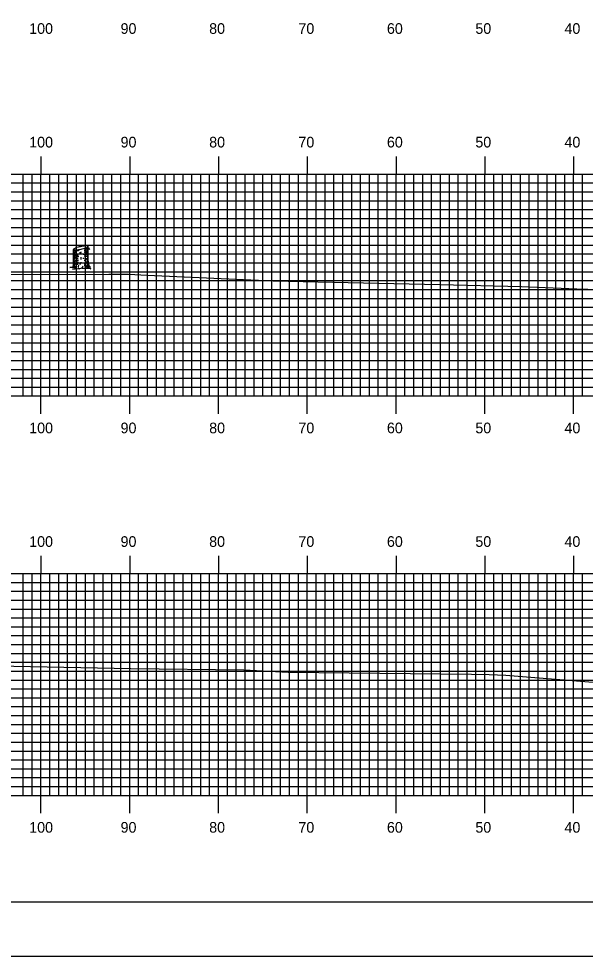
# Model space of a CAD drawing. Extents: x 1772809 to 1773153, y 442591 to 442811.
# Drawn here: x 1772872.6 to 1772936.4, y 442590.5 to 442696.2 of the extents above; entities that cross this region are included whole.
import ezdxf

# ---------------------------------------------------------------- set-up
doc = ezdxf.new("R2010")
doc.units = 0
for name, color, linetype in [('BORDER', 7, 'Continuous'), ('H_V ANNOTATION', 7, 'Continuous'), ('M_Trees_Conifer_Pay', 7, 'Continuous'), ('MAJOR', 7, 'Continuous'), ('MINOR', 7, 'Continuous'), ('PLOT BOUNDARY', 7, 'Continuous'), ('S_Roadway_Centerline', 7, 'Continuous')]:
    doc.layers.add(name, color=color, linetype=linetype)

msp = doc.modelspace()

# ---------------------------------------------------------------- linework, layer by layer
at = {"layer": 'BORDER'}
msp.add_lwpolyline([(1772825.52, 442596.67), (1773145.52, 442596.67), (1773145.52, 442806.67), (1772825.52, 442806.67)], close=True, dxfattribs=at)
at = {"layer": 'M_Trees_Conifer_Pay'}
for p, q in [((1772878.78, 442668.46), (1772878.78, 442670.18)), ((1772878.82, 442670.15), (1772878.82, 442669.67)), ((1772878.88, 442670.13), (1772878.88, 442670.04)), ((1772879.01, 442670.13), (1772879.01, 442669.89)), ((1772879.23, 442670.15), (1772879.23, 442669.98)), ((1772880.02, 442670.19), (1772880.02, 442669.99)), ((1772880.25, 442670.38), (1772880.25, 442670.16)), ((1772880.25, 442670.07), (1772880.25, 442670.03)), ((1772880.37, 442670.45), (1772880.37, 442670.28)), ((1772880.37, 442670.22), (1772880.37, 442670.09)), ((1772880.44, 442668.87), (1772880.44, 442670.52)), ((1772878.82, 442669.61), (1772878.82, 442669.3)), ((1772878.82, 442669.25), (1772878.82, 442668.76)), ((1772878.88, 442669.96), (1772878.88, 442669.76)), ((1772878.88, 442669.7), (1772878.88, 442669.5)), ((1772878.88, 442669.45), (1772878.88, 442669.12)), ((1772878.88, 442669.06), (1772878.88, 442668.93)), ((1772879.01, 442669.85), (1772879.01, 442669.78)), ((1772879.01, 442669.38), (1772879.01, 442669.24)), ((1772879.23, 442669.74), (1772879.23, 442669.5)), ((1772879.23, 442669.26), (1772879.23, 442669.11)), ((1772879.23, 442669.06), (1772879.23, 442668.89)), ((1772879.63, 442669.92), (1772879.63, 442669.82)), ((1772879.63, 442669.3), (1772879.63, 442669.23)), ((1772879.63, 442669.2), (1772879.63, 442669.05)), ((1772880.02, 442669.93), (1772880.02, 442669.84)), ((1772880.02, 442669.5), (1772880.02, 442669.39)), ((1772880.02, 442669.02), (1772880.02, 442668.88)), ((1772880.25, 442669.69), (1772880.25, 442669.56)), ((1772880.25, 442669.45), (1772880.25, 442669.34)), ((1772880.25, 442669.2), (1772880.25, 442669.06)), ((1772880.31, 442669.89), (1772880.26, 442669.83)), ((1772880.37, 442669.9), (1772880.37, 442669.56)), ((1772880.37, 442669.53), (1772880.37, 442669.37)), ((1772880.37, 442669.32), (1772880.37, 442669.1)), ((1772880.37, 442669.07), (1772880.37, 442669)), ((1772878.82, 442668.71), (1772878.82, 442668.46)), ((1772878.88, 442668.83), (1772878.88, 442668.45)), ((1772879.01, 442668.97), (1772879.01, 442668.82)), ((1772879.01, 442668.56), (1772879.01, 442668.47)), ((1772879.01, 442668.07), (1772879.17, 442668.13)), ((1772879.23, 442668.61), (1772879.23, 442668.46)), ((1772879.44, 442668), (1772879.32, 442668.07)), ((1772879.63, 442668.76), (1772879.63, 442668.61)), ((1772880.02, 442668.64), (1772880.02, 442668.56)), ((1772880.25, 442668.83), (1772880.25, 442668.66)), ((1772880.37, 442668.96), (1772880.37, 442668.78))]:
    msp.add_line(p, q, dxfattribs=at)
for points in [[(1772880.26, 442670.02), (1772880.29, 442669.94), (1772880.34, 442670), (1772880.4, 442670.07), (1772880.49, 442670.26), (1772880.56, 442670.31), (1772880.59, 442670.31)], [(1772880.27, 442669.76), (1772880.31, 442669.89), (1772880.37, 442670.01), (1772880.4, 442670.07), (1772880.47, 442670.22)], [(1772880.49, 442670.25), (1772880.56, 442670.26), (1772880.63, 442670.16)], [(1772878.96, 442669.49), (1772878.95, 442669.58), (1772878.99, 442669.56), (1772878.99, 442669.47)], [(1772880.09, 442669.09), (1772880.11, 442669.01), (1772880.15, 442669.02), (1772880.14, 442669.19)], [(1772880.22, 442669.98), (1772880.19, 442669.89), (1772880.19, 442669.83), (1772880.22, 442669.76)], [(1772880.44, 442668.87), (1772880.49, 442668.61), (1772880.51, 442668.34), (1772880.57, 442668.21), (1772880.7, 442668.18), (1772880.47, 442668.14), (1772880.47, 442668.14), (1772880.48, 442668.09), (1772880.72, 442668), (1772880.45, 442668.02), (1772880.09, 442668.04), (1772879.77, 442668.03), (1772879.78, 442668.11), (1772879.63, 442668.03), (1772879.44, 442668), (1772879.47, 442667.94), (1772879.2, 442667.98), (1772878.98, 442667.95), (1772878.69, 442667.97), (1772878.98, 442668.03), (1772879.01, 442668.07), (1772878.84, 442668.13), (1772878.61, 442668.14), (1772878.37, 442668.14), (1772878.71, 442668.19), (1772878.75, 442668.27), (1772878.78, 442668.46)], [(1772878.82, 442668.41), (1772878.8, 442668.34), (1772878.78, 442668.24)], [(1772878.9, 442668.39), (1772878.91, 442668.28), (1772878.86, 442668.19), (1772878.84, 442668.13)], [(1772879.07, 442668.42), (1772879.07, 442668.29), (1772878.98, 442668.19)], [(1772879.29, 442668.18), (1772879.36, 442668.27), (1772879.39, 442668.41)], [(1772879.78, 442668.11), (1772879.85, 442668.25), (1772879.86, 442668.35)], [(1772880.03, 442668.48), (1772880.04, 442668.35), (1772880.12, 442668.31)], [(1772880.31, 442668.09), (1772880.29, 442668.23), (1772880.22, 442668.36)], [(1772880.27, 442668.58), (1772880.34, 442668.48), (1772880.35, 442668.3), (1772880.47, 442668.14)], [(1772880.37, 442668.73), (1772880.37, 442668.58), (1772880.42, 442668.51), (1772880.43, 442668.32)]]:
    msp.add_lwpolyline(points, dxfattribs=at)
for centre, radius, start, end in [((1772878.85, 442670.16), 0.0817, 132.3887, 146.7194), ((1772878.83, 442670.17), 0.0527, 146.7194, 156.5158), ((1772878.81, 442670.18), 0.0314, 156.5158, 169.2194), ((1772878.8, 442670.18), 0.0264, 169.2194, 180.0315), ((1772878.8, 442670.18), 0.0226, 180.0315, 191.7194), ((1772878.8, 442670.18), 0.0226, 191.7194, 203.4074), ((1772878.8, 442670.18), 0.0264, 203.4074, 214.2194), ((1772878.81, 442670.19), 0.0314, 214.2194, 226.923), ((1772878.82, 442670.2), 0.0527, 226.923, 236.7194), ((1772878.84, 442670.23), 0.0817, 236.7194, 251.0501), ((1772878.97, 442670.03), 0.251, 124.2194, 132.3887), ((1772878.89, 442670.39), 0.251, 251.0501, 259.2194), ((1772879.28, 442669.58), 0.802, 108.0594, 124.2194), ((1772879, 442670.93), 0.802, 259.2194, 275.3794), ((1772880.63, 442665.42), 5.18, 101.7194, 108.0594), ((1772878.58, 442675.29), 5.18, 275.3794, 281.7194), ((1772879.61, 442674.19), 4.12, 264.6955, 266.7331), ((1772880.63, 442665.42), 5.18, 95.3794, 101.7194), ((1772878.58, 442675.29), 5.18, 281.7194, 288.0594), ((1772879.61, 442674.19), 4.12, 276.238, 278.1032), ((1772880.22, 442669.77), 0.802, 79.2194, 95.3794), ((1772879.94, 442671.12), 0.802, 288.0594, 304.2194), ((1772880.11, 442670.68), 0.571, 278.1032, 284.3667), ((1772880.11, 442670.83), 0.571, 284.4317, 292.4132), ((1772880.33, 442670.31), 0.251, 71.0501, 79.2194), ((1772880.11, 442670.68), 0.571, 297.0237, 300), ((1772880.25, 442670.67), 0.251, 304.2194, 312.3887), ((1772880.31, 442670.49), 0.172, 300, 311.2506), ((1772880.31, 442670.33), 0.172, 300, 311.2506), ((1772880.38, 442670.47), 0.0817, 56.7194, 71.0501), ((1772880.4, 442670.5), 0.0527, 46.923, 56.7194), ((1772880.37, 442670.54), 0.0817, 312.3887, 326.7194), ((1772880.38, 442670.4), 0.0624, 311.2506, 330), ((1772880.38, 442670.25), 0.0624, 311.2506, 330), ((1772880.41, 442670.51), 0.0314, 34.2194, 46.923), ((1772880.39, 442670.53), 0.0527, 326.7194, 336.5158), ((1772880.42, 442670.52), 0.0226, 11.7194, 23.4074), ((1772880.41, 442670.52), 0.0264, 23.4074, 34.2194), ((1772880.41, 442670.52), 0.0264, 349.2194, 0.0315), ((1772880.42, 442670.52), 0.0226, 0.0315, 11.7194), ((1772880.41, 442670.52), 0.0314, 336.5158, 349.2194), ((1772880.41, 442670.39), 0.0334, 343.9485, 354.2151), ((1772880.4, 442670.39), 0.0441, 330, 343.9485), ((1772880.4, 442670.24), 0.0441, 330, 343.9485), ((1772880.41, 442670.24), 0.0334, 343.9485, 354.2151), ((1772878.81, 442670), 0.0334, 163.9485, 180), ((1772878.81, 442670), 0.0334, 180, 196.0515), ((1772878.82, 442670.01), 0.0441, 196.0515, 210), ((1772878.83, 442670.02), 0.0624, 210, 228.7494), ((1772878.81, 442669.56), 0.0334, 163.9485, 180), ((1772878.81, 442669.56), 0.0334, 180, 196.0515), ((1772878.82, 442669.56), 0.0441, 196.0515, 210), ((1772878.83, 442669.57), 0.0624, 210, 228.7494), ((1772878.81, 442669.35), 0.0334, 163.9485, 180), ((1772878.81, 442669.35), 0.0334, 180, 196.0515), ((1772878.82, 442669.35), 0.0441, 196.0515, 210), ((1772878.83, 442669.36), 0.0624, 210, 228.7494), ((1772878.81, 442669.11), 0.0334, 163.9485, 180), ((1772878.81, 442669.11), 0.0334, 180, 196.0515), ((1772878.82, 442669.11), 0.0441, 196.0515, 210), ((1772878.83, 442669.12), 0.0624, 210, 228.7494), ((1772878.91, 442670.1), 0.172, 228.7494, 240), ((1772878.91, 442669.65), 0.172, 228.7494, 240), ((1772878.91, 442669.44), 0.172, 228.7494, 240), ((1772878.91, 442669.21), 0.172, 228.7494, 240), ((1772879.11, 442670.44), 0.571, 240, 240.3367), ((1772879.11, 442670.23), 0.571, 240, 247.0587), ((1772879.11, 442670), 0.571, 240, 240.3367), ((1772879.11, 442669.79), 0.571, 240, 246.8597), ((1772879.11, 442669.55), 0.571, 240, 246.8597), ((1772879.11, 442670.44), 0.571, 246.8597, 257.9846), ((1772879.11, 442669.79), 0.571, 259.2707, 261.8968), ((1772879.61, 442673.31), 4.12, 261.8968, 263.1474), ((1772879.61, 442673.52), 4.12, 264.081, 266.6676), ((1772879.61, 442673.96), 4.12, 268.0751, 270), ((1772879.61, 442673.96), 4.12, 270, 270.3581), ((1772879.61, 442673.31), 4.12, 270, 270.3581), ((1772879.61, 442673.31), 4.12, 273.1493, 275.4569), ((1772879.61, 442673.75), 4.12, 273.7052, 275.9504), ((1772879.61, 442673.96), 4.12, 275.7849, 277.0558), ((1772879.61, 442673.52), 4.12, 277.6125, 278.1032), ((1772880.11, 442670), 0.571, 278.1032, 286.9296), ((1772880.11, 442670.23), 0.571, 284.4493, 297.0429), ((1772880.11, 442669.55), 0.571, 285.3983, 297.1896), ((1772880.11, 442670), 0.571, 297.1896, 300), ((1772880.11, 442669.79), 0.571, 297.1896, 300), ((1772880.31, 442669.65), 0.172, 300, 311.2506), ((1772880.31, 442669.44), 0.172, 300, 311.2506), ((1772880.38, 442669.57), 0.0624, 311.2506, 330), ((1772880.38, 442669.36), 0.0624, 311.2506, 330), ((1772880.4, 442669.56), 0.0441, 330, 343.9485), ((1772880.4, 442669.35), 0.0441, 330, 343.9485), ((1772880.41, 442669.79), 0.0334, 343.9485, 354.2151), ((1772880.41, 442669.56), 0.0334, 343.9485, 354.2151), ((1772880.41, 442669.35), 0.0334, 343.9485, 354.2151), ((1772878.81, 442668.91), 0.0334, 163.9485, 180), ((1772878.81, 442668.72), 0.0334, 163.9485, 180), ((1772878.81, 442668.72), 0.0334, 180, 196.0515), ((1772878.82, 442668.72), 0.0441, 196.0515, 210), ((1772878.83, 442668.73), 0.0624, 210, 228.7494), ((1772878.81, 442668.5), 0.0334, 163.9485, 180), ((1772878.81, 442668.5), 0.0334, 180, 196.0515), ((1772878.82, 442668.5), 0.0441, 196.0515, 210), ((1772878.83, 442668.51), 0.0624, 210, 228.7494), ((1772878.91, 442668.81), 0.172, 228.7494, 240), ((1772878.91, 442668.59), 0.172, 228.7494, 240), ((1772879.1, 442669.36), 0.571, 241.2369, 248.0268), ((1772879.11, 442669.16), 0.571, 240, 246.8597), ((1772879.11, 442668.94), 0.571, 240, 244.5314), ((1772879.61, 442672.45), 4.12, 262.4438, 263.512), ((1772879.61, 442672.87), 4.12, 263.4991, 265.8397), ((1772879.61, 442673.07), 4.12, 264.716, 266.3193), ((1772879.61, 442672.67), 4.12, 267.8117, 270), ((1772879.61, 442672.67), 4.12, 270, 270.1328), ((1772879.61, 442672.67), 4.12, 275.7849, 276.7896), ((1772879.61, 442672.45), 4.12, 277.3684, 278.1032), ((1772880.11, 442668.94), 0.571, 278.1032, 281.637), ((1772880.11, 442669.16), 0.571, 288.5067, 297.2721), ((1772880.11, 442669.35), 0.571, 289.2907, 300), ((1772880.31, 442669.01), 0.172, 300, 311.2506), ((1772880.31, 442668.59), 0.172, 300, 311.2506), ((1772880.38, 442668.93), 0.0624, 311.2506, 330), ((1772880.38, 442668.51), 0.0624, 311.2506, 330), ((1772880.4, 442668.92), 0.0441, 330, 343.9485), ((1772880.4, 442668.5), 0.0441, 330, 343.9485), ((1772880.41, 442668.91), 0.0334, 343.9485, 354.2151), ((1772880.41, 442668.5), 0.0334, 343.9485, 354.2151)]:
    msp.add_arc(centre, radius, start, end, dxfattribs=at)
at = {"layer": 'MAJOR'}
for p, q in [((1772875.12, 442680.67), (1772875.12, 442678.67)), ((1772885.12, 442680.67), (1772885.12, 442678.67)), ((1772895.12, 442680.67), (1772895.12, 442678.67)), ((1772905.12, 442680.67), (1772905.12, 442678.67)), ((1772915.12, 442680.67), (1772915.12, 442678.67)), ((1772925.12, 442680.67), (1772925.12, 442678.67)), ((1772935.12, 442680.67), (1772935.12, 442678.67)), ((1772835.12, 442678.67), (1773115.12, 442678.67)), ((1772835.12, 442678.67), (1773115.12, 442678.67)), ((1772875.12, 442653.67), (1772875.12, 442678.67)), ((1772885.12, 442653.67), (1772885.12, 442678.67)), ((1772895.12, 442653.67), (1772895.12, 442678.67)), ((1772905.12, 442653.67), (1772905.12, 442678.67)), ((1772915.12, 442653.67), (1772915.12, 442678.67)), ((1772925.12, 442653.67), (1772925.12, 442678.67)), ((1772935.12, 442653.67), (1772935.12, 442678.67)), ((1772835.12, 442673.67), (1773115.12, 442673.67)), ((1772835.12, 442668.67), (1773115.12, 442668.67)), ((1772835.12, 442663.67), (1773115.12, 442663.67)), ((1772835.12, 442658.67), (1773115.12, 442658.67)), ((1772835.12, 442653.67), (1773115.12, 442653.67)), ((1772835.12, 442653.67), (1773115.12, 442653.67)), ((1772875.12, 442651.66), (1772875.12, 442653.67)), ((1772885.12, 442651.66), (1772885.12, 442653.67)), ((1772895.12, 442651.66), (1772895.12, 442653.67)), ((1772905.12, 442651.66), (1772905.12, 442653.67)), ((1772915.12, 442651.66), (1772915.12, 442653.67)), ((1772925.12, 442651.66), (1772925.12, 442653.67)), ((1772935.12, 442651.66), (1772935.12, 442653.67)), ((1772875.12, 442635.67), (1772875.12, 442633.67)), ((1772885.12, 442635.67), (1772885.12, 442633.67)), ((1772895.12, 442635.67), (1772895.12, 442633.67)), ((1772905.12, 442635.67), (1772905.12, 442633.67)), ((1772915.12, 442635.67), (1772915.12, 442633.67)), ((1772925.12, 442635.67), (1772925.12, 442633.67)), ((1772935.12, 442635.67), (1772935.12, 442633.67)), ((1772835.12, 442633.67), (1773115.12, 442633.67)), ((1772835.12, 442633.67), (1773115.12, 442633.67)), ((1772875.12, 442608.67), (1772875.12, 442633.67)), ((1772885.12, 442608.67), (1772885.12, 442633.67)), ((1772895.12, 442608.67), (1772895.12, 442633.67)), ((1772905.12, 442608.67), (1772905.12, 442633.67)), ((1772915.12, 442608.67), (1772915.12, 442633.67)), ((1772925.12, 442608.67), (1772925.12, 442633.67)), ((1772935.12, 442608.67), (1772935.12, 442633.67)), ((1772835.12, 442628.67), (1773115.12, 442628.67)), ((1772835.12, 442623.67), (1773115.12, 442623.67)), ((1772835.12, 442618.67), (1773115.12, 442618.67)), ((1772835.12, 442613.67), (1773115.12, 442613.67)), ((1772835.12, 442608.67), (1773115.12, 442608.67)), ((1772835.12, 442608.67), (1773115.12, 442608.67)), ((1772875.12, 442606.66), (1772875.12, 442608.67)), ((1772885.12, 442606.66), (1772885.12, 442608.67)), ((1772895.12, 442606.66), (1772895.12, 442608.67)), ((1772905.12, 442606.66), (1772905.12, 442608.67)), ((1772915.12, 442606.66), (1772915.12, 442608.67)), ((1772925.12, 442606.66), (1772925.12, 442608.67)), ((1772935.12, 442606.66), (1772935.12, 442608.67))]:
    msp.add_line(p, q, dxfattribs=at)
at = {"layer": 'MINOR'}
for p, q in [((1772873.12, 442653.67), (1772873.12, 442678.67)), ((1772874.12, 442653.67), (1772874.12, 442678.67)), ((1772876.12, 442653.67), (1772876.12, 442678.67)), ((1772877.12, 442653.67), (1772877.12, 442678.67)), ((1772878.12, 442653.67), (1772878.12, 442678.67)), ((1772879.12, 442653.67), (1772879.12, 442678.67)), ((1772880.12, 442653.67), (1772880.12, 442678.67)), ((1772881.12, 442653.67), (1772881.12, 442678.67)), ((1772882.12, 442653.67), (1772882.12, 442678.67)), ((1772883.12, 442653.67), (1772883.12, 442678.67)), ((1772884.12, 442653.67), (1772884.12, 442678.67)), ((1772886.12, 442653.67), (1772886.12, 442678.67)), ((1772887.12, 442653.67), (1772887.12, 442678.67)), ((1772888.12, 442653.67), (1772888.12, 442678.67)), ((1772889.12, 442653.67), (1772889.12, 442678.67)), ((1772890.12, 442653.67), (1772890.12, 442678.67)), ((1772891.12, 442653.67), (1772891.12, 442678.67)), ((1772892.12, 442653.67), (1772892.12, 442678.67)), ((1772893.12, 442653.67), (1772893.12, 442678.67)), ((1772894.12, 442653.67), (1772894.12, 442678.67)), ((1772896.12, 442653.67), (1772896.12, 442678.67)), ((1772897.12, 442653.67), (1772897.12, 442678.67)), ((1772898.12, 442653.67), (1772898.12, 442678.67)), ((1772899.12, 442653.67), (1772899.12, 442678.67)), ((1772900.12, 442653.67), (1772900.12, 442678.67)), ((1772901.12, 442653.67), (1772901.12, 442678.67)), ((1772902.12, 442653.67), (1772902.12, 442678.67)), ((1772903.12, 442653.67), (1772903.12, 442678.67)), ((1772904.12, 442653.67), (1772904.12, 442678.67)), ((1772906.12, 442653.67), (1772906.12, 442678.67)), ((1772907.12, 442653.67), (1772907.12, 442678.67)), ((1772908.12, 442653.67), (1772908.12, 442678.67)), ((1772909.12, 442653.67), (1772909.12, 442678.67)), ((1772910.12, 442653.67), (1772910.12, 442678.67)), ((1772911.12, 442653.67), (1772911.12, 442678.67)), ((1772912.12, 442653.67), (1772912.12, 442678.67)), ((1772913.12, 442653.67), (1772913.12, 442678.67)), ((1772914.12, 442653.67), (1772914.12, 442678.67)), ((1772916.12, 442653.67), (1772916.12, 442678.67)), ((1772917.12, 442653.67), (1772917.12, 442678.67)), ((1772918.12, 442653.67), (1772918.12, 442678.67)), ((1772919.12, 442653.67), (1772919.12, 442678.67)), ((1772920.12, 442653.67), (1772920.12, 442678.67)), ((1772921.12, 442653.67), (1772921.12, 442678.67)), ((1772922.12, 442653.67), (1772922.12, 442678.67)), ((1772923.12, 442653.67), (1772923.12, 442678.67)), ((1772924.12, 442653.67), (1772924.12, 442678.67)), ((1772926.12, 442653.67), (1772926.12, 442678.67)), ((1772927.12, 442653.67), (1772927.12, 442678.67)), ((1772928.12, 442653.67), (1772928.12, 442678.67)), ((1772929.12, 442653.67), (1772929.12, 442678.67)), ((1772930.12, 442653.67), (1772930.12, 442678.67)), ((1772931.12, 442653.67), (1772931.12, 442678.67)), ((1772932.12, 442653.67), (1772932.12, 442678.67)), ((1772933.12, 442653.67), (1772933.12, 442678.67)), ((1772934.12, 442653.67), (1772934.12, 442678.67)), ((1772936.12, 442653.67), (1772936.12, 442678.67)), ((1772835.12, 442677.67), (1773115.12, 442677.67)), ((1772835.12, 442676.67), (1773115.12, 442676.67)), ((1772835.12, 442675.67), (1773115.12, 442675.67)), ((1772835.12, 442674.67), (1773115.12, 442674.67)), ((1772835.12, 442672.67), (1773115.12, 442672.67)), ((1772835.12, 442671.67), (1773115.12, 442671.67)), ((1772835.12, 442670.67), (1773115.12, 442670.67)), ((1772835.12, 442669.67), (1773115.12, 442669.67)), ((1772835.12, 442667.67), (1773115.12, 442667.67)), ((1772835.12, 442666.67), (1773115.12, 442666.67)), ((1772835.12, 442665.67), (1773115.12, 442665.67)), ((1772835.12, 442664.67), (1773115.12, 442664.67)), ((1772835.12, 442662.67), (1773115.12, 442662.67)), ((1772835.12, 442661.67), (1773115.12, 442661.67)), ((1772835.12, 442660.67), (1773115.12, 442660.67)), ((1772835.12, 442659.67), (1773115.12, 442659.67)), ((1772835.12, 442657.67), (1773115.12, 442657.67)), ((1772835.12, 442656.67), (1773115.12, 442656.67)), ((1772835.12, 442655.67), (1773115.12, 442655.67)), ((1772835.12, 442654.67), (1773115.12, 442654.67)), ((1772873.12, 442608.67), (1772873.12, 442633.67)), ((1772874.12, 442608.67), (1772874.12, 442633.67)), ((1772876.12, 442608.67), (1772876.12, 442633.67)), ((1772877.12, 442608.67), (1772877.12, 442633.67)), ((1772878.12, 442608.67), (1772878.12, 442633.67)), ((1772879.12, 442608.67), (1772879.12, 442633.67)), ((1772880.12, 442608.67), (1772880.12, 442633.67)), ((1772881.12, 442608.67), (1772881.12, 442633.67)), ((1772882.12, 442608.67), (1772882.12, 442633.67)), ((1772883.12, 442608.67), (1772883.12, 442633.67)), ((1772884.12, 442608.67), (1772884.12, 442633.67)), ((1772886.12, 442608.67), (1772886.12, 442633.67)), ((1772887.12, 442608.67), (1772887.12, 442633.67)), ((1772888.12, 442608.67), (1772888.12, 442633.67)), ((1772889.12, 442608.67), (1772889.12, 442633.67)), ((1772890.12, 442608.67), (1772890.12, 442633.67)), ((1772891.12, 442608.67), (1772891.12, 442633.67)), ((1772892.12, 442608.67), (1772892.12, 442633.67)), ((1772893.12, 442608.67), (1772893.12, 442633.67)), ((1772894.12, 442608.67), (1772894.12, 442633.67)), ((1772896.12, 442608.67), (1772896.12, 442633.67)), ((1772897.12, 442608.67), (1772897.12, 442633.67)), ((1772898.12, 442608.67), (1772898.12, 442633.67)), ((1772899.12, 442608.67), (1772899.12, 442633.67)), ((1772900.12, 442608.67), (1772900.12, 442633.67)), ((1772901.12, 442608.67), (1772901.12, 442633.67)), ((1772902.12, 442608.67), (1772902.12, 442633.67)), ((1772903.12, 442608.67), (1772903.12, 442633.67)), ((1772904.12, 442608.67), (1772904.12, 442633.67)), ((1772906.12, 442608.67), (1772906.12, 442633.67)), ((1772907.12, 442608.67), (1772907.12, 442633.67)), ((1772908.12, 442608.67), (1772908.12, 442633.67)), ((1772909.12, 442608.67), (1772909.12, 442633.67)), ((1772910.12, 442608.67), (1772910.12, 442633.67)), ((1772911.12, 442608.67), (1772911.12, 442633.67)), ((1772912.12, 442608.67), (1772912.12, 442633.67)), ((1772913.12, 442608.67), (1772913.12, 442633.67)), ((1772914.12, 442608.67), (1772914.12, 442633.67)), ((1772916.12, 442608.67), (1772916.12, 442633.67)), ((1772917.12, 442608.67), (1772917.12, 442633.67)), ((1772918.12, 442608.67), (1772918.12, 442633.67)), ((1772919.12, 442608.67), (1772919.12, 442633.67)), ((1772920.12, 442608.67), (1772920.12, 442633.67)), ((1772921.12, 442608.67), (1772921.12, 442633.67)), ((1772922.12, 442608.67), (1772922.12, 442633.67)), ((1772923.12, 442608.67), (1772923.12, 442633.67)), ((1772924.12, 442608.67), (1772924.12, 442633.67)), ((1772926.12, 442608.67), (1772926.12, 442633.67)), ((1772927.12, 442608.67), (1772927.12, 442633.67)), ((1772928.12, 442608.67), (1772928.12, 442633.67)), ((1772929.12, 442608.67), (1772929.12, 442633.67)), ((1772930.12, 442608.67), (1772930.12, 442633.67)), ((1772931.12, 442608.67), (1772931.12, 442633.67)), ((1772932.12, 442608.67), (1772932.12, 442633.67)), ((1772933.12, 442608.67), (1772933.12, 442633.67)), ((1772934.12, 442608.67), (1772934.12, 442633.67)), ((1772936.12, 442608.67), (1772936.12, 442633.67)), ((1772835.12, 442632.67), (1773115.12, 442632.67)), ((1772835.12, 442631.67), (1773115.12, 442631.67)), ((1772835.12, 442630.67), (1773115.12, 442630.67)), ((1772835.12, 442629.67), (1773115.12, 442629.67)), ((1772835.12, 442627.67), (1773115.12, 442627.67)), ((1772835.12, 442626.67), (1773115.12, 442626.67)), ((1772835.12, 442625.67), (1773115.12, 442625.67)), ((1772835.12, 442624.67), (1773115.12, 442624.67)), ((1772835.12, 442622.67), (1773115.12, 442622.67)), ((1772835.12, 442621.67), (1773115.12, 442621.67)), ((1772835.12, 442620.67), (1773115.12, 442620.67)), ((1772835.12, 442619.67), (1773115.12, 442619.67)), ((1772835.12, 442617.67), (1773115.12, 442617.67)), ((1772835.12, 442616.67), (1773115.12, 442616.67)), ((1772835.12, 442615.67), (1773115.12, 442615.67)), ((1772835.12, 442614.67), (1773115.12, 442614.67)), ((1772835.12, 442612.67), (1773115.12, 442612.67)), ((1772835.12, 442611.67), (1773115.12, 442611.67)), ((1772835.12, 442610.67), (1773115.12, 442610.67)), ((1772835.12, 442609.67), (1773115.12, 442609.67))]:
    msp.add_line(p, q, dxfattribs=at)
at = {"layer": 'PLOT BOUNDARY'}
msp.add_lwpolyline([(1772809.33, 442590.55), (1773149.33, 442590.55), (1773149.33, 442810.55), (1772809.33, 442810.55)], close=True, dxfattribs=at)
at = {"layer": 'S_Roadway_Centerline'}
for points in [[(1772835.12, 442668.15), (1772838.69, 442667.99), (1772845.07, 442668.09), (1772857.08, 442667.77), (1772862.21, 442667.41), (1772866.54, 442667.34), (1772882.78, 442667.38), (1772884.99, 442667.38), (1772887.09, 442667.3), (1772901.27, 442666.64), (1772908.01, 442666.48), (1772920.06, 442666.22), (1772929.24, 442666.01), (1772935.48, 442665.74), (1772951.58, 442665.24)], [(1772835.12, 442624.38), (1772843.63, 442624.06), (1772845.8, 442623.99), (1772847.9, 442623.96), (1772865.35, 442623.55), (1772872.07, 442623.24), (1772885.25, 442622.96), (1772897.99, 442622.8), (1772902.98, 442622.54), (1772923.61, 442622.34), (1772925.62, 442622.3), (1772927.49, 442622.2), (1772938.72, 442621.3)]]:
    msp.add_lwpolyline(points, dxfattribs=at)

# ---------------------------------------------------------------- texts
at = {"layer": 'H_V ANNOTATION'}
for s, p in [('100', (1772873.8, 442694.47)), ('90', (1772884.09, 442694.47)), ('80', (1772894.07, 442694.47)), ('70', (1772904.12, 442694.47)), ('60', (1772914.09, 442694.47)), ('50', (1772924.05, 442694.47)), ('40', (1772934.09, 442694.47)), ('100', (1772873.8, 442681.67)), ('90', (1772884.09, 442681.67)), ('80', (1772894.07, 442681.67)), ('70', (1772904.12, 442681.67)), ('60', (1772914.09, 442681.67)), ('50', (1772924.05, 442681.67)), ('40', (1772934.09, 442681.67)), ('100', (1772873.8, 442649.47)), ('90', (1772884.09, 442649.47)), ('80', (1772894.07, 442649.47)), ('70', (1772904.12, 442649.47)), ('60', (1772914.09, 442649.47)), ('50', (1772924.05, 442649.47)), ('40', (1772934.09, 442649.47)), ('100', (1772873.8, 442636.67)), ('90', (1772884.09, 442636.67)), ('80', (1772894.07, 442636.67)), ('70', (1772904.12, 442636.67)), ('60', (1772914.09, 442636.67)), ('50', (1772924.05, 442636.67)), ('40', (1772934.09, 442636.67)), ('100', (1772873.8, 442604.47)), ('90', (1772884.09, 442604.47)), ('80', (1772894.07, 442604.47)), ('70', (1772904.12, 442604.47)), ('60', (1772914.09, 442604.47)), ('50', (1772924.05, 442604.47)), ('40', (1772934.09, 442604.47))]:
    msp.add_text(s, height=1.2, dxfattribs=at).set_placement(p)

doc.saveas('drawing.dxf')
